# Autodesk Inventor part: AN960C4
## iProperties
Created: 2005-10
Part Number: AN960C4
Material: Stainless Steel, Austenitic
Description: Washer, Fl, #4
Document SubType Name: Modeling
Designer: B. Foreman
Title: AN960 Flat Washers
Author: B. Foreman
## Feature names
1. Extrusion1
